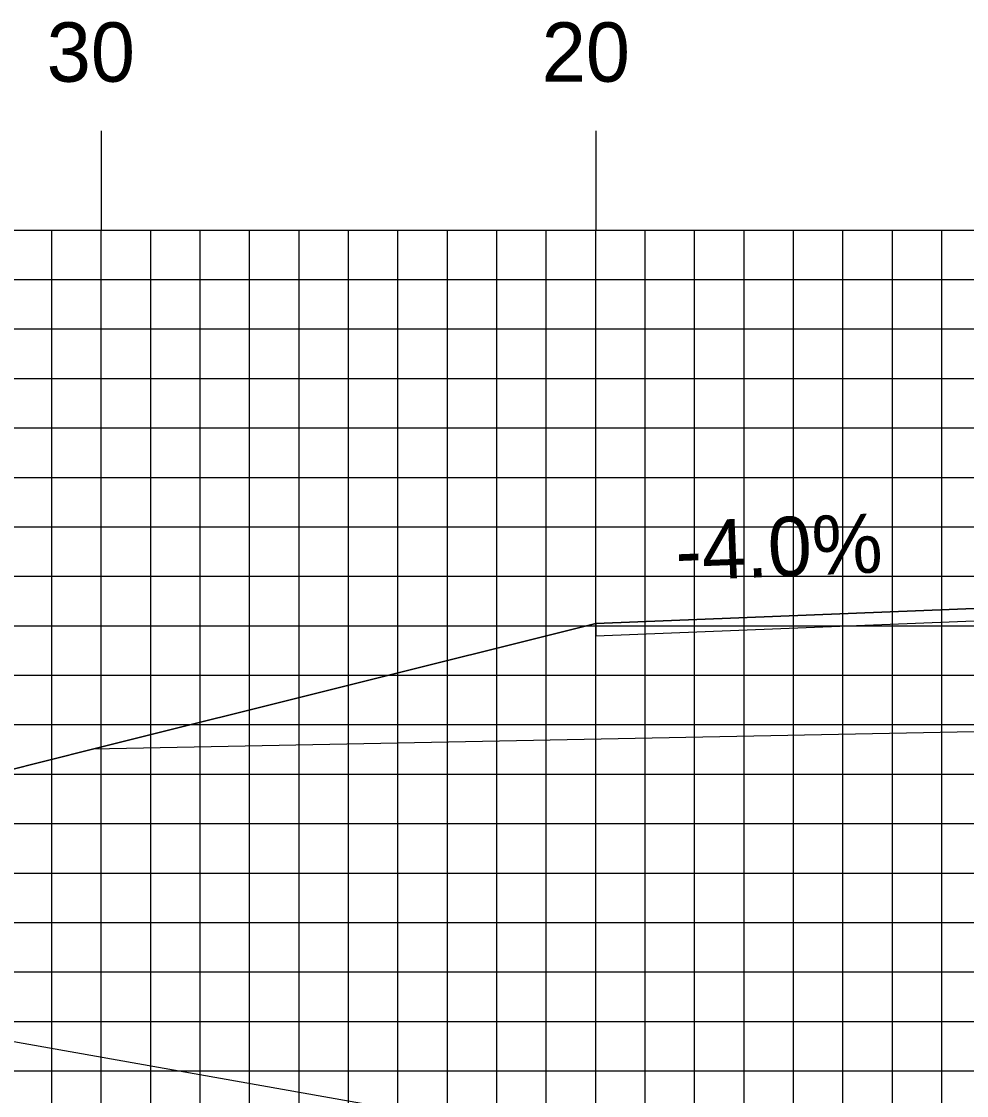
# Model space of a CAD drawing. Extents: x 1815702 to 1816046, y 442591 to 442811.
# Drawn here: x 1815836.43 to 1815855.55, y 442731.17 to 442752.88 of the extents above; entities that cross this region are included whole.
import ezdxf

# ---------------------------------------------------------------- set-up
doc = ezdxf.new("R2010")
doc.units = 0
for name, color, linetype in [('ANNOTATION', 7, 'Continuous'), ('D_Roadway_Centerline', 7, 'Continuous'), ('D_Roadway_Edge_Shoulder', 7, 'Continuous'), ('D_Roadway_SlopeLines', 7, 'Continuous'), ('D_Roadway_SubGrade', 7, 'Continuous'), ('H_V ANNOTATION', 7, 'Continuous'), ('MAJOR', 7, 'Continuous'), ('MINOR', 7, 'Continuous'), ('S_Roadway_Centerline', 7, 'Continuous')]:
    doc.layers.add(name, color=color, linetype=linetype)

msp = doc.modelspace()

# ---------------------------------------------------------------- linework, layer by layer
at = {"layer": 'D_Roadway_Centerline'}
msp.add_lwpolyline([(1815820.648, 442733.859), (1815836.047, 442737.709), (1815837.873, 442738.166), (1815848.047, 442740.709), (1815856.047, 442741.029), (1815868.047, 442741.269), (1815880.047, 442741.029), (1815888.047, 442740.709), (1815898.221, 442738.166), (1815900.047, 442737.709), (1815942.232, 442723.647)], dxfattribs=at)
at = {"layer": 'D_Roadway_Edge_Shoulder'}
msp.add_lwpolyline([(1815856.047, 442741.029), (1815848.047, 442740.709), (1815848.047, 442740.459), (1815856.047, 442740.779)], close=True, dxfattribs=at)
at = {"layer": 'D_Roadway_SlopeLines'}
msp.add_lwpolyline([(1815848.047, 442740.709), (1815837.873, 442738.166), (1815836.047, 442737.709), (1815820.648, 442733.859)], dxfattribs=at)
at = {"layer": 'D_Roadway_SubGrade'}
msp.add_lwpolyline([(1815856.047, 442738.529), (1815837.873, 442738.166), (1815848.047, 442740.709), (1815848.047, 442740.459), (1815856.047, 442740.779), (1815868.047, 442741.019), (1815880.047, 442740.779), (1815888.047, 442740.459), (1815888.047, 442740.709), (1815898.221, 442738.166), (1815880.047, 442738.529), (1815868.047, 442738.769)], close=True, dxfattribs=at)
at = {"layer": 'MAJOR'}
for p, q in [((1815838.047, 442750.669), (1815838.047, 442748.665)), ((1815848.047, 442750.669), (1815848.047, 442748.665)), ((1815728.047, 442748.665), (1816008.047, 442748.665)), ((1815728.047, 442748.665), (1816008.047, 442748.665)), ((1815838.047, 442713.665), (1815838.047, 442748.665)), ((1815848.047, 442713.665), (1815848.047, 442748.665)), ((1815728.047, 442743.665), (1816008.047, 442743.665)), ((1815728.047, 442738.665), (1816008.047, 442738.665)), ((1815728.047, 442733.665), (1816008.047, 442733.665))]:
    msp.add_line(p, q, dxfattribs=at)
at = {"layer": 'MINOR'}
for p, q in [((1815837.047, 442713.665), (1815837.047, 442748.665)), ((1815839.047, 442713.665), (1815839.047, 442748.665)), ((1815840.047, 442713.665), (1815840.047, 442748.665)), ((1815841.047, 442713.665), (1815841.047, 442748.665)), ((1815842.047, 442713.665), (1815842.047, 442748.665)), ((1815843.047, 442713.665), (1815843.047, 442748.665)), ((1815844.047, 442713.665), (1815844.047, 442748.665)), ((1815845.047, 442713.665), (1815845.047, 442748.665)), ((1815846.047, 442713.665), (1815846.047, 442748.665)), ((1815847.047, 442713.665), (1815847.047, 442748.665)), ((1815849.047, 442713.665), (1815849.047, 442748.665)), ((1815850.047, 442713.665), (1815850.047, 442748.665)), ((1815851.047, 442713.665), (1815851.047, 442748.665)), ((1815852.047, 442713.665), (1815852.047, 442748.665)), ((1815853.047, 442713.665), (1815853.047, 442748.665)), ((1815854.047, 442713.665), (1815854.047, 442748.665)), ((1815855.047, 442713.665), (1815855.047, 442748.665)), ((1815728.047, 442747.665), (1816008.047, 442747.665)), ((1815728.047, 442746.665), (1816008.047, 442746.665)), ((1815728.047, 442745.665), (1816008.047, 442745.665)), ((1815728.047, 442744.665), (1816008.047, 442744.665)), ((1815728.047, 442742.665), (1816008.047, 442742.665)), ((1815728.047, 442741.665), (1816008.047, 442741.665)), ((1815728.047, 442740.665), (1816008.047, 442740.665)), ((1815728.047, 442739.665), (1816008.047, 442739.665)), ((1815728.047, 442737.665), (1816008.047, 442737.665)), ((1815728.047, 442736.665), (1816008.047, 442736.665)), ((1815728.047, 442735.665), (1816008.047, 442735.665)), ((1815728.047, 442734.665), (1816008.047, 442734.665)), ((1815728.047, 442732.665), (1816008.047, 442732.665)), ((1815728.047, 442731.665), (1816008.047, 442731.665))]:
    msp.add_line(p, q, dxfattribs=at)
at = {"layer": 'S_Roadway_Centerline'}
msp.add_lwpolyline([(1815813.519, 442734.442), (1815817.669, 442734.085), (1815831.045, 442733.072), (1815831.857, 442733.018), (1815834.906, 442732.5), (1815845.169, 442730.68), (1815847.186, 442730.502), (1815858.008, 442729.871), (1815863.977, 442729.579), (1815871.952, 442729.261), (1815881.085, 442728.476), (1815884.611, 442728.07), (1815898.479, 442726.849), (1815912.254, 442725.064), (1815915.396, 442724.993), (1815920.236, 442724.754), (1815932.352, 442724.248), (1815944.057, 442723.536), (1815950.072, 442723.217)], dxfattribs=at)

# ---------------------------------------------------------------- texts
at = {"layer": 'ANNOTATION'}
msp.add_text('-4.0%', height=1.2, rotation=2.2906, dxfattribs=at).set_placement((1815849.679, 442741.576))
at = {"layer": 'H_V ANNOTATION'}
for s, p in [('30', (1815836.944, 442751.665)), ('20', (1815846.955, 442751.665))]:
    msp.add_text(s, height=1.2, dxfattribs=at).set_placement(p)

doc.saveas('drawing.dxf')
